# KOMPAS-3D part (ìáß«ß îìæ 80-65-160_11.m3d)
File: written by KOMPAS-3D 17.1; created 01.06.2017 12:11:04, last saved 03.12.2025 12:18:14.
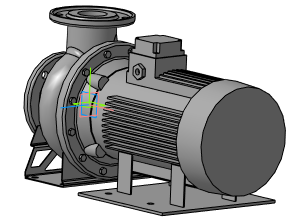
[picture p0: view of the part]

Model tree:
1. Операция без истории:3

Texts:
  ООО АДЛ ГРУПП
